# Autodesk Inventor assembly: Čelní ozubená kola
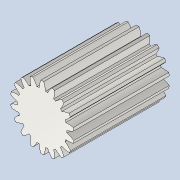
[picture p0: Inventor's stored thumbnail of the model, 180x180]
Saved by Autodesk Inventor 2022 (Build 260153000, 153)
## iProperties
ClientObjectVersion: 1
Created: 2025-05
Part Number: Čelní ozubená kola
Document SubType Name: Assembly
Designer: jbart
Categories: <?xml version="1.0" encoding="UTF-16"?> <MemberInstance><Categories><FamilyTemplate/><ParamToTemplateMap><ParamToTemplate><ParamToTemplate CategoryParameter="//
Author: jbart
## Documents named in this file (2)
- C:\Users\jbart\OneDrive\Dokumenty\Inventor\Převodovka navijáku\Satelit B\Design Accelerator\Čelní ozubená kola1.iam
- C:\Users\jbart\OneDrive\Dokumenty\Inventor\Převodovka navijáku\Satelit B\Design Accelerator\Čelní ozubené kolo11.ipt
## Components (1 placed, 1 different names)
1. Čelní ozubené kolo1:1
